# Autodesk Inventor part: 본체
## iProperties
Company: 한국ATC센터
Created: 2014-10
Part Number: 본체
Document SubType Name: Modeling
Designer: 한국ATC센터
Density: 2.71 g/cm^3
Material: 알루미늄-6061
Mass: 3285.44 g
Surface Area: 2358.47 cm^2
Volume: 1212.34 cm^3
Author: KYOUNG IL JANG
